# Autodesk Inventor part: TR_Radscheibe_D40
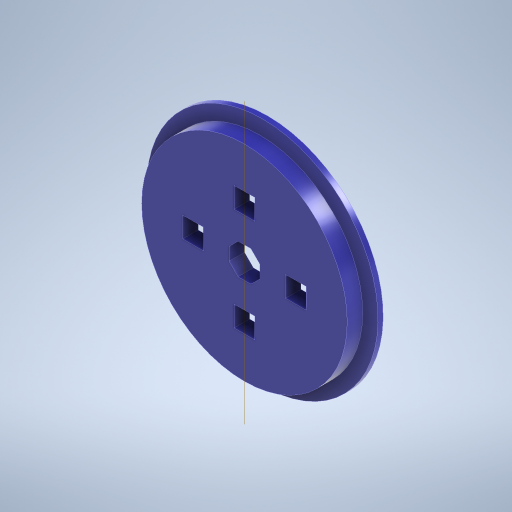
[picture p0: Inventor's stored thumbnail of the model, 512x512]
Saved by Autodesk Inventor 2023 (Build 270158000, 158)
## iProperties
Created: 2023-11
Part Number: TR_Radscheibe_D40
Material: PC/ABS-Kunststoff
Document SubType Name: Modeling
Designer: Administrator
Density: 0.357273 g/cm^3
Appearance: Glatt - Marine
Author: Administrator
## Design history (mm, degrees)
sketch "Skizze1"
  geometry: L1 (0, 0)-(0, -3); L2 (0, -3)-(17.5, -3); L3 (17.5, -3)-(17.5, -4.5); L4 (17.5, -4.5)-(22.5, -4.5); L5 (22.5, -4.5)-(22.5, -3.5); L6 (22.5, -3.5)-(20, -3); L7 (20, -3)-(20, 0); L8 (20, 0)-(0, 0)
  constraints: 16 end point, 5 perpendicular, 1 parallel, 1 vertical
  dimensions: "d0" = 3 distance of L1.start L1.end; "d1" = 4.5 distance from line of L1.start L4; "d2" = 1 distance of L5.end L4.end; "d3" = 1.5 vertical distance of L4.end L6.end; "d5" = 20 distance between parallel lines of L1 L7; "d6" = 22.5 horizontal distance of L1.start L5.end; "d32" = 17.5 horizontal distance of L1.start L3.end
revolve "Umdrehung1" sketch "Skizze1" stored, may be unused: angle "d7" = 90 deg
sketch "Skizze2"
  geometry: L1 (3, -1.243)-(1.243, -3); L2 (1.243, -3)-(-1.243, -3); L3 (-1.243, -3)-(-3, -1.243); L4 (-3, -1.243)-(-3, 1.243); L5 (-3, 1.243)-(-1.243, 3); L6 (-1.243, 3)-(1.243, 3); L7 (1.243, 3)-(3, 1.243); L8 (3, 1.243)-(3, -1.243); 2 further points
  constraints: 16 end point, 1 coincident, 1 horizontal, 17 other
  dimensions: "d8" = 6 distance between parallel lines of L8 L4 (= AchteckUmkreis)
extrude "Extrusion1" cut sketch "Skizze2" extent not by distance; stored distance "d9" = 0; taper "d10" = 0 deg
sketch "Skizze6"
  geometry: L1 (-2, 12)-(2, 12); L2 (2, 12)-(2, 8); L3 (2, 8)-(-2, 8); L4 (-2, 8)-(-2, 12); 2 further points
  constraints: 8 end point, 2 parallel, 2 perpendicular, 1 horizontal, 1 midpoint, 1 vertical alignment
  dimensions: "d33" = 4 distance of L1.start L1.end; "d34" = 8 vertical distance of point (0, 0) L3.end
extrude "Extrusion5" cut sketch "Skizze6" distance "d35" = 10; taper "d36" = 0 deg
pattern_circular "Runde Anordnung3" dims angle "d38" = 360 deg
node "Volumenkörper1"
other parameters: "Radius" = 2.075 [user parameter], "Fasen" = 0.5 [user parameter], "Dicke" = 0.8 [user parameter], "Breitloch" = 2 [user parameter], "Langloch" = 32 [user parameter], "AchteckUmkreis" = 6 [user parameter; used in 1 equation term], "DAchsAufnahme" = 4.1 [user parameter], "AchsDurchmesser" = 4 [user parameter], "AchsFase" = 0.5 [user parameter]
